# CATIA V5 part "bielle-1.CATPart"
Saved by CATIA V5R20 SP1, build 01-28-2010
Part number: bielle-1
Bounding box of the stored display mesh (mm): x -135.357 to 4.643, y 23.235 to 53.235, z 0 to 30
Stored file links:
  C:\Users\Manon\Desktop\IAO\Pieces\bielle-1.CATPart
  C:\Users\Manon\Desktop\IAO\assemblage\Assemblage_rlanglais.CATProduct
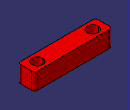
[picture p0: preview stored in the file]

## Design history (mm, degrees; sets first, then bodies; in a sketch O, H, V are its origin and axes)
External parameters (linked from other documents)
  External.bielle_1 = 100 mm
Body1 (main body)
  Sketch1 on xy-plane, origin (0, 0, 0), H (1, 0, 0), V (0, 1, 0)
    line L1 (-135.3568, 53.2349) -> (4.6432, 53.2349)
    line L2 (4.6432, 53.2349) -> (4.6432, 23.2349)
    line L3 (4.6432, 23.2349) -> (-135.3568, 23.2349)
    line L4 (-135.3568, 23.2349) -> (-135.3568, 53.2349)
    circle A1 centre (-15.3568, 38.2349) radius 10
    point P5 (-15.3568, 38.2349)
    circle A2 centre (-115.3568, 38.2349) radius 10
    point P6 (-115.3568, 38.2349)
    length L1 = 140
    length L2 = 30
    radius A2 = 10
    radius A1 = 10
    distance P5 P6 = 100 {= External.bielle_1}
    distance P5 L2 = 20
    distance P5 L3 = 15
    horizontal: L1 H, L3 H
    vertical: L2 V, L4 V
  Pad1: profile Sketch1, direction (0, 0, 1), length 30
  Fillet1: radius 5, on edge [face of Pad1 from Sketch1.L1 | face of Pad1 from Sketch1.L2]
  Fillet2: radius 5, on edge [face of Pad1 from Sketch1.L2 | face of Pad1 from Sketch1.L3]; edge [face of Pad1 from Sketch1.L4 | face of Pad1 from Sketch1.L1]
  Fillet3: radius 5, on edge [face of Pad1 from Sketch1.L3 | face of Pad1 from Sketch1.L4]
